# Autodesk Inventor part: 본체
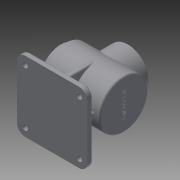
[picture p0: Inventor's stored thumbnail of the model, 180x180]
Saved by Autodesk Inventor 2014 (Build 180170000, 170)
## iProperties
Created: 2015-07
Part Number: 본체
Material: 일반
Document SubType Name: Modeling
Designer: Owner
Density: 1 g/cm^3
Appearance: 기본값
Author: Owner
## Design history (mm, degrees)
sketch "스케치1"
  geometry: L1 (-58.5, 0)-(58.5, 0); L2 (-58.5, 27)-(-58.5, 38); L3 (-58.5, 38)-(-51.5, 38); L4 (-51.5, 38)-(-51.5, 45); L5 (-51.5, 45)-(58.5, 45); L6 (58.5, 45)-(58.5, 0); L7 (-58.5, 27)-(-44.5, 27); L8 (-44.5, 27)-(-44.5, 40); L9 (-44.5, 40)-(51.5, 40); L10 (51.5, 40)-(51.5, 0); 2 further points
  constraints: 20 end point, 5 perpendicular, 4 parallel, 2 vertical alignment, 1 coincident, 1 horizontal, 1 midpoint, 1 point on line
  dimensions: "d0" = 90 diameter of L5 L1; "d1" = 117 distance of L1.start L1.end; "d2" = 54 diameter of L7 L1; "d3" = 80 diameter of L9 L1; "d4" = 7 distance of L2.end L3.end; "d5" = 14 distance of L2.start L7.end; "d6" = 96 distance of L8.end L9.end; "d7" = 76 diameter of L3 L1
revolve "회전1" sketch "스케치1" stored, may be unused: angle "d8" = 90 deg
node "작업 평면1"
sketch "스케치2"
  geometry: L1 (-58.5, 45)-(-58.5, -45) reference; C1 r 38 at (-3.5, 0); 1 further point
  constraints: 1 centre point, 1 horizontal alignment
  dimensions: "d10" = 76 diameter of C1; "d11" = 55 distance from line of C1.centre L1
extrude "돌출1" join sketch "스케치2" stored distance "d12" = 10; taper "d13" = 0 deg
node "작업 평면2"
sketch "스케치3"
  geometry: L1 (-68.5, 65)-(61.5, 65); L2 (61.5, 65)-(61.5, -65); L3 (61.5, -65)-(-68.5, -65); L4 (-68.5, -65)-(-68.5, 65); L5 (-58.5, 45)-(-58.5, -45) reference; 2 further points
  constraints: 8 end point, 2 parallel, 1 horizontal, 1 horizontal alignment, 1 midpoint, 1 perpendicular
  dimensions: "d15" = 130 distance of L2.end L3.end; "d16" = 130 distance of L1.end L2.end; "d17" = 10 distance between parallel lines of L4 L5
extrude "돌출2" join sketch "스케치3" distance "d18" = 10; taper "d19" = 0 deg
fillet "모깎기1" dims "d20" = 15
sketch "스케치5"
  geometry: C1 r 7.5 at (-46.5, -50); A1 r 15 centre (-46.5, -50) between (-61.5, -50) and (-46.5, -65) reference; 1 further point
  constraints: 1 centre point, 1 coincident
  dimensions: "d21" = 15 diameter of C1
extrude "돌출3" join sketch "스케치5" distance "d22" = 3; taper "d23" = 0 deg
hole "구멍1" diameter "d26" = 10; stored, may be unused: countersink angle "d30" = 90 deg, drill point angle "d32" = 118 deg; dims "d24" = 10, "d25" = 10, "d27" = 6, "d28" = 4, "d29" = 2, "d31" = 8
fillet "모깎기2" dims "d33" = 3
node "작업 평면3"
sketch "스케치6"
  geometry: L1 (0, 10)-(100, 10) reference; L2 (5, 10)-(5, 78); L3 (95, 10)-(95, 78); A1 r 45 centre (50, 78) between (5, 78) and (95, 78) reference; 1 further point
  constraints: 4 end point, 2 point on circle, 2 point on line, 1 parallel, 1 perpendicular
  dimensions: "d40" = 45 distance from line of point (50, 78) L2; "d41" = 90 distance between parallel lines of L2 L3
extrude "돌출4" join sketch "스케치6" stored distance "d42" = 10; taper "d43" = 0 deg
node "작업 평면4"
sketch "스케치7"
  geometry: L1 (0, 10)-(100, 10) reference; L2 (105, 33)-(-5, 33) reference; L3 (5, 10)-(5, 33); L4 (95, 10)-(95, 33); L5 (55, 78)-(45, 78) reference; L6 (100, 0)-(0, 0) reference; L7 (45, 78)-(45, 10) reference; L8 (55, 10)-(55, 78) reference; L9 (45, 10)-(55, 10) reference; L10 (100, 10)-(0, 10) reference; L11 (-15, 0)-(-15, 10) reference; 2 further points
  constraints: 4 end point, 4 point on line, 2 perpendicular, 1 midpoint
  dimensions: "d44" = 90 distance between parallel lines of L4 L3; "d45" = 65 distance from line of point (50, 10) L11; "d46" = 45 distance from line of point (50, 10) L3
extrude "돌출5" join sketch "스케치7" stored distance "d47" = 10; taper "d48" = 0 deg
hole "구멍2" diameter "d51" = 54; stored, may be unused: countersink angle "d55" = 90 deg, drill point angle "d57" = 118 deg; dims "d49" = 10, "d50" = 10, "d52" = 6, "d53" = 4, "d54" = 2, "d56" = 8
sketch "스케치8"
  geometry: C1 r 38 at (0, 0) reference; 1 further point
  constraints: 1 vertical alignment
  dimensions: "d58" = 32 distance of point (0, 32) C1.centre
hole "구멍3" sketch "스케치8" at (0, 32) diameter "d59" = 3.242; stored, may be unused: countersink angle "d63" = 90 deg, drill point angle "d65" = 118 deg; dims "d60" = 8, "d61" = 4, "d62" = 2, "d64" = 10
sketch "스케치9"
  geometry: C1 r 27 at (0, 0) reference; 2 further points
  constraints: 1 vertical alignment
  dimensions: "d69" = 32 distance of point (0, 32) C1.centre
hole "구멍4" sketch "스케치9" at (0, 32) diameter "d70" = 3.242; stored, may be unused: countersink angle "d74" = 90 deg, drill point angle "d76" = 118 deg; dims "d71" = 8, "d72" = 4, "d73" = 2, "d75" = 10
fillet "모깎기3" dims "d80" = 3
fillet "모깎기4" dims "d81" = 3
fillet "모깎기5" dims "d82" = 3
fillet "모깎기6" dims "d83" = 3
fillet "모깎기7" dims "d84" = 3
chamfer "모따기1" distance "d85" = 1; stored, may be unused: second distance "d86" = 2, angle "d87" = 45 deg
fillet "모깎기8" dims "d88" = 3
fillet "모깎기9" dims "d89" = 3
sketch "스케치10"
  geometry: C1 r 42 at (0, 0) reference; 1 further point
  constraints: 1 coincident, 1 other
feature "엠보싱1" sketch "스케치10" dims "d90" = 0.5, "d91" = 0
node "솔리드1"
pattern_linear "직사각형 패턴1"
pattern_circular "원형 패턴1" dims angle "d67" = 360 deg
pattern_circular "원형 패턴2" dims angle "d78" = 360 deg
other parameters: "d9" = 62, "d14" = -78
